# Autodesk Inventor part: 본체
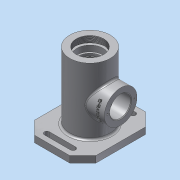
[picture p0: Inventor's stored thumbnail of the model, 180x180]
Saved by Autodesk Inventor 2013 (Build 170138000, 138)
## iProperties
Created: 2017-10
Part Number: 본체
Material: 알루미늄 6061
Document SubType Name: Modeling
Designer: dgall
Density: 2.71 g/cm^3
Mass: 738.316 g
Surface Area: 651.732 cm^2
Volume: 272.441 cm^3
Author: dgall
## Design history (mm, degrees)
sketch "스케치1"
  geometry: L1 (0, 0)-(94, 0); L2 (94, 0)-(94, -116); L3 (94, -116)-(0, -116); L4 (0, -116)-(0, 0)
  constraints: 8 end point, 2 parallel, 1 horizontal, 1 perpendicular
  dimensions: "d0" = 94 distance of L1.start L1.end; "d1" = 116 distance of L3.end L1.start
extrude "돌출1" new body sketch "스케치1" distance "d2" = 10; taper "d3" = 0 deg
chamfer "모따기1" distance "d11" = 20; stored, may be unused: second distance "d12" = 2, angle "d13" = 45 deg
sketch "스케치3"
  geometry: L1 (-94, -20)-(-94, -96) reference; L2 (-20, 0)-(-74, 0) reference; C1 r 35 at (-47, -58); 3 further points
  constraints: 2 midpoint, 1 centre point, 1 horizontal alignment, 1 vertical alignment
  dimensions: "d14" = 70 diameter of C1
extrude "돌출3" join sketch "스케치3" distance "d16" = 3; taper "d17" = 0 deg
sketch "스케치4"
  geometry: L1 (74, 0)-(20, 0) reference; L2 (94, -96)-(94, -20) reference; C1 r 31 at (47, -58); 4 further points
  constraints: 3 midpoint, 1 centre point, 1 horizontal alignment, 1 vertical alignment
  dimensions: "d18" = 62 diameter of C1
extrude "돌출4" join sketch "스케치4" distance "d20" = 102; taper "d21" = 0 deg
node "작업 평면1"
sketch "스케치5"
  geometry: L1 (-10, 96)-(0, 96) reference; L2 (0, 96)-(0, 73) reference; L3 (0, 73)-(3, 73) reference; L4 (3, 73)-(3, 3) reference; L5 (3, 3)-(0, 3) reference; L6 (0, 3)-(0, -20) reference; L7 (0, -20)-(-10, -20) reference; L8 (-10, -20)-(-10, 7) reference; L9 (-10, 7)-(-112, 7) reference; L10 (-112, 7)-(-112, 69) reference; L11 (-112, 69)-(-10, 69) reference; L12 (-10, 69)-(-10, 96) reference; L13 (-112, 38)-(3, 38); L14 (-112, 59)-(-103, 59); L15 (-103, 59)-(-103, 62); L16 (-103, 62)-(-100, 62); L17 (-100, 62)-(-100, 58); L18 (-100, 58)-(-91, 58); L19 (-91, 58)-(-91, 55.5); L20 (-91, 55.5)-(-87.75, 55.5); L21 (-87.75, 55.5)-(-87.75, 56.5); L22 (-87.75, 56.5)-(-86, 56.5); L23 (-86, 56.5)-(-86, 55.5); L24 (-86, 55.5)-(-75, 55.5); L25 (-75, 55.5)-(-75, 64); L26 (-75, 64)-(-37, 64); L27 (-37, 64)-(-37, 55.5); L28 (-37, 55.5)-(-26, 55.5); L29 (-26, 55.5)-(-26, 54.5); L30 (-26, 54.5)-(-21, 54.5); L31 (-21, 54.5)-(-21, 48); L32 (-21, 48)-(-18.3, 48); L33 (-18.3, 48)-(-18.3, 50.5); L34 (-18.3, 50.5)-(-11, 50.5); L35 (-11, 50.5)-(-11, 54); L36 (-11, 54)-(3, 60)
  constraints: 48 end point, 20 parallel, 2 horizontal alignment, 2 midpoint, 2 perpendicular, 2 point on line
  dimensions: "d22" = 42 diameter of L14 L13; "d24" = 48 diameter of L16 L13; "d25" = 12 distance between parallel lines of L17 L10; "d26" = 3 distance of L15.end L16.end; "d27" = 21 distance between parallel lines of L19 L10; "d28" = 40 diameter of L18 L13; "d30" = 35 diameter of L20 L13; "d31" = 37 diameter of L22 L13; "d32" = 1.75 distance of L21.end L22.end; "d33" = 26 distance between parallel lines of L23 L10; "d34" = 52 diameter of L26 L13; "d35" = 38 distance between parallel lines of L27 L25; "d36" = 11 distance of L23.end L24.end; "d37" = 11 distance of L27.end L28.end; "d38" = 33 diameter of L30 L13; "d39" = 5 distance of L29.end L30.end; "d40" = 2.7 distance of L31.end L32.end; "d42" = 20 diameter of L32 L13; "d43" = 25 diameter of L34 L13; "d45" = 7.3 distance of L33.end L34.end; "d55" = 32 diameter of L35.end L13; "d56" = 44 diameter of L36.end L13
revolve "회전1" sketch "스케치5" stored, may be unused: angle "d47" = 90 deg
feature "스레드1" dims "d48" = 10, "d49" = 0
chamfer "모따기2" distance "d51" = 1; stored, may be unused: second distance "d52" = 2, angle "d53" = 45 deg
fillet "모깎기2" dims "d54" = 0.3
fillet "모깎기3" dims "d57" = 3
fillet "모깎기4" dims "d58" = 0.3
node "작업 평면3"
  node "작업 평면2"
sketch "스케치6"
  geometry: L1 (-112, 69)-(-112, 7) reference; C1 r 25 at (-56, 38); 2 further points
  constraints: 1 centre point, 1 horizontal alignment, 1 midpoint
  dimensions: "d63" = 50 diameter of C1; "d65" = 56 distance of C1.centre point (-112, 38)
extrude "돌출5" join sketch "스케치6" stored distance "d66" = 102; taper "d67" = 0 deg
sketch "스케치7"
  geometry: C1 r 25 at (0, 0) reference; C2 r 16 at (0, 0); 1 further point
  constraints: 1 centre point, 1 coincident
  dimensions: "d68" = 32 diameter of C2
extrude "돌출6" cut sketch "스케치7" stored distance "d70" = 102; taper "d71" = 0 deg
chamfer "모따기4" distance "d72" = 1; stored, may be unused: second distance "d73" = 2, angle "d74" = 30 deg
fillet "모깎기5" dims "d75" = 3
sketch "스케치8"
  geometry: C1 r 25 at (0, 0) reference; C2 r 17 at (0, 0) reference; A1 r 20.5 centre (0, 0) between (0, 20.5) and (0, -20.5); 1 further point
  constraints: 2 point on circle, 2 vertical alignment, 1 centre point, 1 coincident
  dimensions: "d76" = 41 diameter of A1
hole "구멍1" sketch "스케치8" at (0, 20.5), (0, -20.5) diameter "d78" = 2.459; stored, may be unused: countersink angle "d82" = 82 deg, drill point angle "d84" = 118 deg; dims "d79" = 6, "d80" = 3.023, "d81" = 2, "d83" = 8
node "작업 평면4"
sketch "스케치9"
  geometry: L1 (94, 81)-(94, 31) reference; L2 (78, 112)-(16, 112) reference; 2 further points
  constraints: 1 other
  dimensions: "d86" = 10 distance from line of point (84, 56) L1; "d87" = 56 distance from line of point (84, 56) L2
feature "엠보싱1" sketch "스케치9" dims "d0" = 94, "d1" = 116, "d88" = 0.5, "d89" = 0
sketch "스케치10"
  geometry: L1 (-20, 0)-(-74, 0) reference; L2 (-67, -108)-(-27, -108); L3 (-67, -100)-(-27, -100); L4 (-67, -16)-(-27, -16); L5 (-67, -8)-(-27, -8); C1 r 35 at (-47, -58) reference; A1 r 4 centre (-67, -104) between (-67, -100) and (-67, -108); A2 r 4 centre (-27, -104) between (-27, -108) and (-27, -100); A3 r 4 centre (-67, -12) between (-67, -8) and (-67, -16); A4 r 4 centre (-27, -12) between (-27, -16) and (-27, -8); 1 further point
  constraints: 8 end point, 8 point on circle, 7 tangent, 4 centre point, 3 equal radius, 2 horizontal alignment, 2 vertical alignment, 1 parallel
  dimensions: "d90" = 4 radius of A1; "d92" = 46 vertical distance of C1.centre A1.centre; "d93" = 92 distance of A3.centre A1.centre; "d94" = 20 horizontal distance of C1.centre A1.centre; "d95" = 40 distance of A1.centre A2.centre
extrude "돌출7" cut sketch "스케치10" stored distance "d96" = 102; taper "d97" = 0 deg
chamfer "모따기5" distance "d98" = 0.7; stored, may be unused: second distance "d99" = 2, angle "d100" = 30 deg
node "솔리드1"
node "절단 모서리 투영1"
other parameters: "d62" = 47, "d85" = -144.25
